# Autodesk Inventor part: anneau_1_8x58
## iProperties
Created: 2011-01
Part Number: anneau_1_8x58
Document SubType Name: Modeling
Designer: eric
Density: 1 g/cm^3
Mass: 0.463674 g
Surface Area: 10.3039 cm^2
Volume: 0.463674 cm^3
Author: eric
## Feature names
1. Base1
